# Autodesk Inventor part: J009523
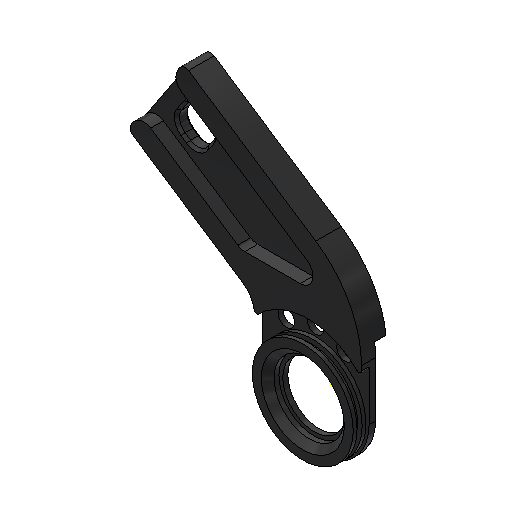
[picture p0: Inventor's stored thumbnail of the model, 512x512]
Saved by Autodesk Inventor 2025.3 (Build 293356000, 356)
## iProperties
RuleStatus: InUse
AfterDocSave0: file://Part Number Cleaner
Created: 2014-10
Material: TITANIUM, 6AL-4V, ANNEALED
Vendor: HHMI: JRC - JET
Document SubType Name: Modeling
Designer: arnoldj
Density: 4.43 g/cm^3
Description: MBS INLINE RING TAB THIN
Mass: 2.07661 g
Surface Area: 8.87594 cm^2
Volume: 0.468761 cm^3
Project: COMMON
Appearance: Dark Gray
Sheet Metal Rule: Default
Part Number: J009523
DESIGN DEPARTMENT: HHMI: JRC - ID&F
SPECIAL FINISH: NONE
LAB/DEPT: COMMON
REQUESTING SCIENTIST: COMMON
SURFACE ROUGHNESS: 63 Ra
Thickness: 0.100 in
ALTERED ITEM PART NUMBER: N/A
ALTERED ITEM VENDOR: N/A
ALTERED ITEM DESCRIPTION: N/A
Revision Number: -
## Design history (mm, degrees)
sketch "Sketch1"
  geometry: L1 (-5.334, -5)-(-5.334, 6.031); L2 (-5.334, 6.031)-(-5.334, -2.635); L3 (-5.334, 6.031)-(-17.956, 14.385); L4 (-17.956, 14.385)-(-12.418, 22.752); L5 (-12.418, 22.752)-(5.334, 11.002); L6 (-17.956, 14.385)-(-30.248, 14.385); L7 (-15.187, 18.569)-(0, 8.517); L8 (-12.15, 14.274)-(-10.048, 17.451); L9 (-10.048, 17.451)-(-12.716, 19.218); L10 (-12.716, 19.218)-(-14.819, 16.041); L11 (-14.819, 16.041)-(-12.15, 14.274); L12 (-12.15, 14.274)-(-12.716, 19.218); L13 (-10.048, 17.451)-(-14.819, 16.041); L14 (5.334, -5)-(5.334, 11.002); L15 (0, 29.009)-(0, -14.79) reference; L16 (-38.853, 0)-(21.379, 0) reference; L17 (-5.334, -5)-(5.334, -5); C1 r 3.5 at (0, 0); C2 r 3.5 at (0, 0); 6 further points
  constraints: 30 end point, 4 coincident, 4 parallel, 4 point on line, 3 midpoint, 3 perpendicular, 3 vertical, 2 centre point, 2 horizontal, 1 concentric
  dimensions: "d161" = 123.5 deg angle of L3 L1; "d162" = 10.033 distance of L3.end L4.end; "d177" = 146.5 deg angle of L3 L6 (derived); "d221" = 3.302 distance from line of point (-12.433, 16.746) L4; "d232" = 3.2004 distance of L8.end L9.end; "d233" = 3.81 distance of L8.start L8.end; "d262" = 7 diameter of C1; "d267" = 0 distance from line of L16 point (0, 0); "d271" = 16.74603 vertical distance of point (-12.433, 16.746) C2.centre; "d273" = 5.334 distance from line of C1.centre L1; "d274" = 1.834 distance edge to line of C1 L1 (derived); "d275" = 5.334 distance from line of C1.centre L14; "d320" = 0 distance from line of L15 C1.centre; "d321" = 5 distance from line of C1.centre L17; "d430" = 12.43338 distance from line of point (-12.433, 16.746) L15
node "Face1"
node "CenterPoint1"
workplane "Work Plane1"
sketch "Sketch7" dims "d343" = 12.065
  geometry: L1 (0, 23.237)-(0, -13.828) reference; L2 (-5.334, -5)-(-5.334, 6.031) reference; L3 (-22.672, 0)-(18.682, 0) reference; C1 r 0.826 at (0, 6.032); C2 r 0.826 at (-2.921, 5.169); C3 r 0.826 at (2.921, 5.169); C4 r 0.826 at (-2.108, 6.992); C5 r 0.826 at (2.108, 6.992); C6 r 3.5 at (0, 0) reference; A1 r 7.302 centre (0, 0) between (2.108, 6.992) and (-2.108, 6.992); 5 further points
  constraints: 6 centre point, 5 coincident, 4 equal radius, 2 point on circle, 1 vertical alignment, 2 other
  dimensions: "d61" = 1.651 diameter of C1; "d344" = 14.605 diameter of A1; "d345" = 2.921 horizontal distance of C1.centre point (2.921, 5.169); "d346" = 2.921 horizontal distance of point (-2.921, 5.169) C1.centre; "d347" = 2.1082 distance from line of L1 point (2.108, 6.992); "d348" = 2.1082 distance from line of L1 C4.centre
hole "Hole2" sketch "Sketch7" diameter "d66" = 1.651; stored, may be unused: countersink angle "d70" = 82 deg, drill point angle "d72" = 118 deg; dims "d67" = 19.05, "d68" = 9.525, "d69" = 6.35, "d71" = 2.54 (= Thickness)
workplane "Work Plane3"
sketch "Sketch10"
  geometry: C1 r 3.5 at (2.646, -1.251); 1 further point
  constraints: 1 centre point
  dimensions: "d150" = 7 diameter of C1
extrude "Extrusion7" cut sketch "Sketch1" stored distance "d234" = 25.4; taper "d235" = 0 deg
fillet "Fillet19" dims "d236" = 1.27
sketch "Sketch20"
  geometry: L1 (-8.89, 11.849)-(-7.334, 10.819) reference; L2 (-3.626, 8.365)-(-5.989, 9.929) reference; A1 r 0.635 centre (-5.638, 10.458) between (-5.989, 9.929) and (-5.272, 9.94) reference; A2 r 13.658 centre (2.611, -1.214) between (-1.463, 11.823) and (-5.272, 9.94) reference; A3 r 0.635 centre (-1.652, 12.429) between (-1.463, 11.823) and (-1.302, 12.958) reference; 16 further points; 1 other entity
  constraints: 2 other
extrude "Extrusion11" cut sketch "Sketch20" distance "d293" = 0.508; taper "d294" = 0 deg
chamfer "Chamfer6" distance "d237" = 0.254; stored, may be unused: second distance "d238" = 3.175, angle "d239" = 45 deg
fillet "Fillet20" dims "d240" = 0.635
workplane "Work Plane5"
workplane "Work Plane6"
workaxis "Work Axis1"
fillet "Fillet21" dims "d286" = 2.54
fillet "Fillet22" dims "d287" = 5.08
fillet "Fillet31" dims "d364" = 10.16
workaxis "Work Axis2"
sketch "Sketch25"
  geometry: L1 (1.27, 1.778)-(4.064, 1.778); L2 (5.08, 0.762)-(5.08, 0); L3 (-4.032, 0)-(13.299, 0); L4 (5.08, 0)-(1.27, 0); L5 (1.27, 1.778)-(1.27, 0); L6 (0, -5.063)-(0, 5.705) reference; L7 (1.27, 4.167)-(1.27, -3.525); L8 (-5, 2.54)-(0.08, 2.54) reference; L9 (-5, 2.54)-(-5, 0) reference; A1 r 1.016 centre (4.064, 0.762) between (5.08, 0.762) and (4.064, 1.778); 1 further point
  constraints: 12 end point, 3 point on line, 2 point on circle, 2 tangent, 2 vertical, 1 centre point, 1 perpendicular
  dimensions: "d324" = 2.54 diameter of L6 L7; "d325" = 0 distance between parallel lines of L5 L7; "d326" = 3.81 distance of L1.start point (5.08, 1.778); "d327" = 1.016 radius of A1; "d328" = 0.762 distance between parallel lines of L1 L8; "d352" = 6.27 distance between parallel lines of L5 L9 (derived)
sketch "Sketch27"
  geometry: L1 (-17.605, 14.915)-(-12.769, 22.222) reference; L2 (-11.889, 22.401)-(5.334, 11.002) reference; L3 (-6.472, 6.785)-(-17.426, 14.035) reference; L4 (-16.729, 16.239)-(-13.645, 20.898); L5 (-13.645, 20.898)-(-3.584, 14.239); L6 (-3.584, 14.239)-(-6.668, 9.58); L7 (-6.668, 9.58)-(-16.729, 16.239); L8 (-15.187, 18.569)-(0, 8.517); L9 (-6.668, 9.58)-(-0.764, 9.58); L10 (-3.584, 14.239)-(-0.063, 11.909); A1 r 1.27 centre (-0.764, 10.85) between (-0.764, 9.58) and (-0.063, 11.909); 2 further points
  constraints: 14 end point, 2 parallel, 2 point on circle, 2 point on line, 2 tangent, 1 centre point, 1 collinear, 1 horizontal, 1 midpoint, 1 perpendicular, 1 other
  dimensions: "d334" = 12.065 distance of L4.end L5.end; "d335" = 5.588 distance between parallel lines of L7 L5; "d429" = 2.2225 distance between parallel lines of L2 L5 (derived); "d431" = 1.27 radius of A1
extrude "Extrusion13" cut sketch "Sketch27" distance "d336" = 1.27; taper "d337" = 0 deg
fillet "Fillet26" dims "d338" = 1.27
fillet "Fillet27" dims "d339" = 1.27
chamfer "Chamfer9" distance "d340" = 0.254; stored, may be unused: second distance "d341" = 3.175, angle "d342" = 45 deg
sketch "Sketch28"
  geometry: L1 (-4.127, -5)-(4.128, -5); L2 (4.128, -5)-(4.128, 8.335); L3 (4.128, 8.335)-(-4.128, 8.335); L4 (-4.128, 8.335)-(-4.127, -5); L5 (-4.127, -5)-(4.128, 8.335); L6 (4.128, -5)-(-4.128, 8.335); L7 (-0.254, -5)-(0.254, -5) reference; 2 further points
  constraints: 12 end point, 2 midpoint, 2 parallel, 1 horizontal, 1 perpendicular
  dimensions: "d353" = 8.255 distance of L2.end L3.end; "d354" = 0 distance from line of L7.start L1; "d355" = 13.335 distance of L1.end L2.end
extrude "Extrusion14" cut sketch "Sketch28" distance "d356" = 1.27; taper "d357" = 0 deg
fillet "Fillet28" dims "d358" = 3.175
chamfer "Chamfer10" distance "d360" = 0.381; stored, may be unused: second distance "d361" = 3.175, angle "d362" = 45 deg
fillet "Fillet30" dims "d363" = 0.381
sketch "Sketch33"
  geometry: C1 r 3.5 at (0, 0) reference; C2 r 3.5 at (0, 0); C3 r 4.516 at (0, 0); C4 r 6.929 at (0, 0); C5 r 5.024 at (0, 0); C6 r 1.206 at (-1.676, 5.472); C7 r 0.597 at (-1.676, 5.472); 2 further points
  constraints: 6 centre point, 5 coincident, 2 tangent, 1 concentric
  dimensions: "d383" = 1.016 radial gap between concentric circles of C3 C1; "d384" = 2.413 radial gap between concentric circles of C3 C4; "d395" = 0.508 radial gap between concentric circles of C3 C5; "d396" = 2.413 diameter of C6 (derived); "d397" = 1.1938 diameter of C7
extrude "Extrusion17" cut sketch "Sketch33" distance "d385" = 0.762; taper "d386" = 0 deg
sketch "Sketch37"
  geometry: C1 r 3.5 at (0, 0) reference; C2 r 3.5 at (0, 0); C3 r 4.567 at (0, 0); 1 further point
  constraints: 2 centre point, 1 coincident, 1 concentric
  dimensions: "d419" = 1.0668 radial gap between concentric circles of C1 C3
extrude "Extrusion21" join sketch "Sketch37" distance "d420" = 0.889; taper "d421" = 0 deg
fillet "Fillet32" dims "d393" = 0.254
hole "Hole4" diameter "d400" = 8; stored, may be unused: countersink angle "d404" = 82 deg, drill point angle "d406" = 0 deg; dims "d401" = 19.05, "d402" = 9.525, "d403" = 6.35, "d405" = 0.1524, "d427" = 25.4, "d428" = 25.4
sketch "Sketch23"
  geometry: L1 (-5.334, 11.002)-(11.889, 22.401) reference; L2 (12.769, 22.222)-(17.605, 14.915) reference; L3 (17.426, 14.035)-(6.472, 6.785) reference; L4 (12.38, 22.727)-(17.918, 14.36); L5 (17.918, 14.36)-(10.288, 9.31); L6 (10.288, 9.31)-(4.751, 17.677); L7 (4.751, 17.677)-(12.38, 22.727); L8 (17.605, 14.915)-(12.769, 22.222) reference; 2 further points
  constraints: 8 end point, 3 parallel, 1 perpendicular
  dimensions: "d316" = 9.1948 distance between parallel lines of L2 L6
feature "Simulation Only Cut4" sketch "Sketch23" dims "d317" = 0.0127, "d318" = 0
sketch "Sketch16"
  geometry: C1 r 0.198 at (0, 3.349); C2 r 3.5 at (0, 0) reference; 1 further point
  constraints: 1 centre point, 1 vertical alignment
extrude "Simulation Only Extrusion8" cut sketch "Sketch16" stored distance "d276" = 25.4; taper "d277" = 0 deg
sketch "Sketch35"
  geometry: C1 r 3.5 at (0, 0) reference; C2 r 4 at (0, 0) reference; C3 r 4 at (0, 0) reference; C4 r 3.119 at (0, 0); 1 further point
  constraints: 1 centre point
  dimensions: "d409" = 0.381 radial gap between concentric circles of C1 C4
extrude "Extrusion19" join sketch "Sketch35" distance "d410" = 0.508; taper "d411" = 0 deg
sketch "Sketch36"
  geometry: C1 r 4.516 at (0, 0) reference; C2 r 5.024 at (0, 0) reference; 1 further point
extrude "Extrusion20" join sketch "Sketch36" distance "d417" = 0.381; taper "d418" = 0 deg
sketch "Sketch38"
  geometry: C1 r 5.024 at (0, 0) reference; C2 r 3.5 at (0, 0) reference; 1 further point
extrude "Extrusion22" join sketch "Sketch38" distance "d422" = 0.381; taper "d423" = 0 deg
chamfer "Chamfer13" distance "d424" = 0.635; stored, may be unused: second distance "d425" = 3.175, angle "d426" = 45 deg
sketch "Sketch40"
  geometry: L1 (5.334, 4.666)-(5.334, 0.08) reference; L2 (17.426, 14.035)-(6.472, 6.785) reference; L3 (12.769, 22.222)-(17.605, 14.915) reference; L4 (-0.782, 14.015)-(11.889, 22.401) reference; L5 (-5.334, 0.08)-(-5.334, 5.543) reference; L6 (-4.509, 5.16)-(-4.509, -2.296) reference; L7 (0.952, 8.716)-(-0.952, 8.716) reference; L8 (4.508, -2.296)-(4.508, 5.16) reference; L9 (11.517, 18.729)-(10.966, 18.364) reference; L10 (14.33, 17.24)-(13.629, 18.299) reference; L11 (13.35, 14.763)-(13.9, 15.128) reference; L12 (10.537, 16.252)-(11.238, 15.193) reference; L13 (0, -14.756)-(0, 28.807) reference; L14 (-18.887, 0)-(23.9, 0) reference; L15 (-7.62, 6.858)-(7.62, 6.858); L16 (7.62, 6.858)-(7.62, -5.842); L17 (7.62, -5.842)-(-7.62, -5.842); L18 (-7.62, -5.842)-(-7.62, 6.858); L19 (-7.62, 6.858)-(7.62, -5.842); L20 (7.62, 6.858)-(-7.62, -5.842); C1 r 0.826 at (0, 6.032) reference; A1 r 0.381 centre (4.508, -1.915) between (4.508, -2.296) and (4.853, -2.077) reference; A2 r 5.08 centre (0.254, 0.08) between (4.853, -2.077) and (5.334, 0.08) reference; A3 r 2.54 centre (7.874, 4.666) between (6.472, 6.785) and (5.334, 4.666) reference; A4 r 0.635 centre (17.076, 14.564) between (17.426, 14.035) and (17.605, 14.915) reference; A5 r 0.635 centre (12.239, 21.872) between (12.769, 22.222) and (11.889, 22.401) reference; A6 r 10.16 centre (4.826, 5.543) between (-0.782, 14.015) and (-5.334, 5.543) reference; A7 r 5.08 centre (-0.254, 0.08) between (-5.334, 0.08) and (-4.853, -2.077) reference; A8 r 0.381 centre (-4.509, -1.915) between (-4.853, -2.077) and (-4.509, -2.296) reference; A9 r 3.556 centre (-0.953, 5.16) between (-0.952, 8.716) and (-4.509, 5.16) reference; A10 r 3.556 centre (0.952, 5.16) between (4.508, 5.16) and (0.952, 8.716) reference; A11 r 1.524 centre (11.808, 17.093) between (10.966, 18.364) and (10.537, 16.252) reference; A12 r 1.524 centre (12.358, 17.458) between (13.629, 18.299) and (11.517, 18.729) reference; A13 r 1.524 centre (13.059, 16.399) between (13.9, 15.128) and (14.33, 17.24) reference; A14 r 1.524 centre (12.509, 16.034) between (11.238, 15.193) and (13.35, 14.763) reference; 2 further points
  constraints: 12 end point, 2 midpoint, 2 parallel, 1 horizontal, 1 perpendicular, 1 point on line, 1 tangent
  dimensions: "d433" = 12.7 distance of L15.end L16.end; "d434" = 15.24 distance of L16.end L17.end
extrude "Extrusion23" cut sketch "Sketch40" distance "d435" = 1.143; taper "d436" = 0 deg
body "Solid1"
sketch "Sketch9"
  geometry: 1 further point
sketch "Sketch3"
  geometry: L1 (-4.445, 6.16)-(-16.764, 6.16); L2 (-6.35, 14.16)-(-6.35, 6.16); L3 (0, 17.942)-(0, -8.533); L4 (12.775, 8.279)-(4.445, 8.279); 4 further points; 1 other entity
  constraints: 8 end point, 1 perpendicular, 1 point on line, 4 other
  dimensions: "d15" = 6.35 distance between parallel lines of L3 L2
sketch "Sketch15"
  geometry: 1 further point
sketch "Sketch26"
  geometry: 1 further point
sketch "Sketch29"
  geometry: 1 further point
sketch "Sketch39"
  geometry: 1 further point
face "Plate1" dims "d432" = 2.54 (derived)
node "Projected Loop2"
node "Projected Loop3"
other parameters: "Thickness" = 2.54, "KFactor" = 4.4, "BendRadius" = 2.54 (= Thickness), "BendReliefWidth" = 2.54 (= Thickness), "BendReliefDepth" = 1.27 (= 0.5 x Thickness), "CornerReliefSize" = 10.16 (= 4 x Thickness), "SeamGap" = 0.00508, "MinimumRemnant" = 5.08 (= 2 x Thickness), "TransitionRadius" = 2.54 (= BendRadius), "JacobiRadiusSize" = 2.54 (= BendRadius), "GapSize" = 2.54 (= Thickness), "d6" = 2.54 (= BendRadius), "d52" = 10.16, "d192" = 1.143, "d219" = 2.46, "sa_0" = 0, "sa_1" = 0, "sa_2" = -48.93044, "sa_3" = 0, "sa_4" = 0, "sa_5" = -489.30442, "d299" = 2.46, "d300" = 2.46 (derived), "sa_6" = 0, "sa_7" = 0, "sa_8" = -490.63889
